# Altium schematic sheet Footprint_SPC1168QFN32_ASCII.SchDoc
size A4; 项目编号: SPSZ2023-052501A; 项目名称: 三相PFC-2.2KW压机+700W风机
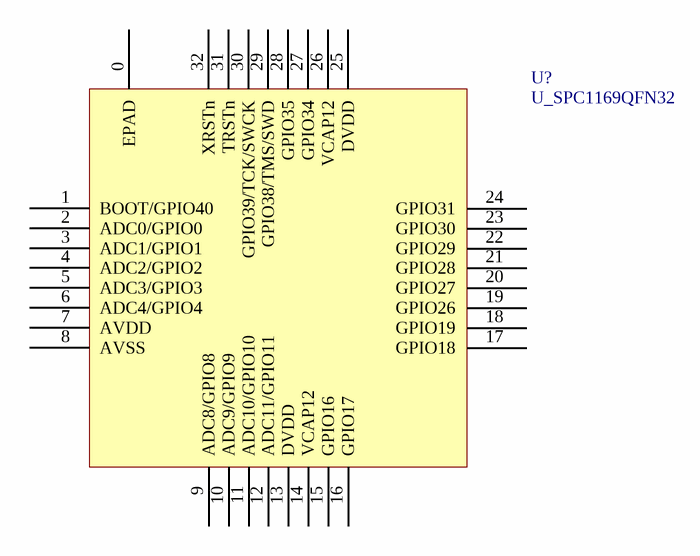
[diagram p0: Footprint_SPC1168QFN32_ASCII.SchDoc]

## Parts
U?  U_SPC1169QFN32

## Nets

Not connected (* = marked no-connect by the designer): U? 0(EPAD) 1(BOOT/GPIO40) 2(ADC0/GPIO0) 3(ADC1/GPIO1) 4(ADC2/GPIO2) 5(ADC3/GPIO3) 6(ADC4/GPIO4) 7(AVDD) 8(AVSS) 9(ADC8/GPIO8) 10(ADC9/GPIO9) 11(ADC10/GPIO10) 12(ADC11/GPIO11) 13(DVDD) 14(VCAP12) 15(GPIO16) 16(GPIO17) 17(GPIO18) 18(GPIO19) 19(GPIO26) 20(GPIO27) 21(GPIO28) 22(GPIO29) 23(GPIO30) 24(GPIO31) 25(DVDD) 26(VCAP12) 27(GPIO34) 28(GPIO35) 29(GPIO38/TMS/SWD) 30(GPIO39/TCK/SWCK) 31(TRSTn) 32(XRSTn)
